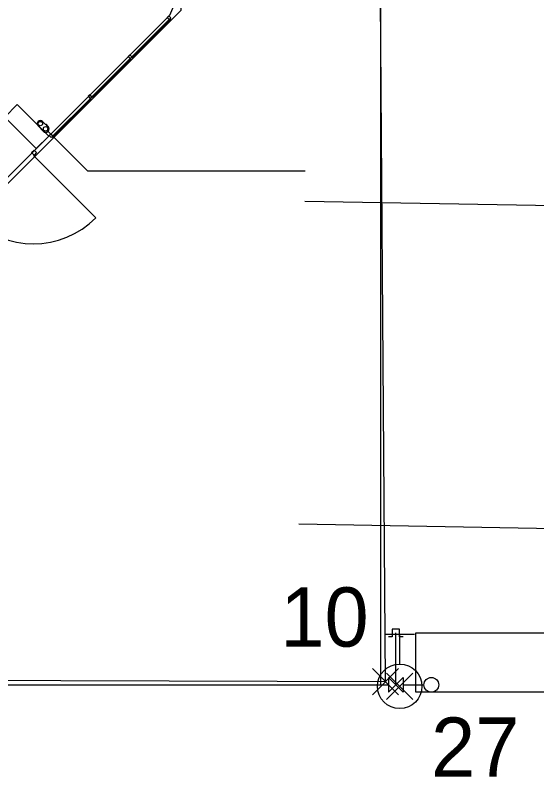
# Model space of a CAD drawing. Extents: x -263964 to -263544, y -1242317 to -1242020.
# Drawn here: x -263800.48 to -263782.89, y -1242253.24 to -1242227.54 of the extents above; entities that cross this region are included whole.
import ezdxf

# ---------------------------------------------------------------- set-up
doc = ezdxf.new("R2010")
doc.units = 0
for name, color, linetype in [('KFA_KOORDINACNA_SITUACIA_DSP_SEDA', 7, 'Continuous'), ('KFA_SO_50-2_POZIARNY_VODOVOD_BODY', 7, 'Continuous'), ('KFA_SO_50-2_POZIARNY_VODOVOD_NADZEMNE_PRVKY', 7, 'Continuous'), ('KFA_SO_50-2_POZIARNY_VODOVOD_TRASA', 7, 'Continuous')]:
    doc.layers.add(name, color=color, linetype=linetype)

msp = doc.modelspace()

# ---------------------------------------------------------------- linework, layer by layer
at = {"layer": 'KFA_KOORDINACNA_SITUACIA_DSP_SEDA'}
for p, q in [((-263788.143, -1242250.14), (-263788.143, -1242082.64)), ((-263795.043, -1242226.995), (-263795.272, -1242227.55)), ((-263795.272, -1242227.55), (-263808.8, -1242241.078)), ((-263796.558, -1242228.963), (-263795.25, -1242227.654)), ((-263795.232, -1242227.672), (-263796.541, -1242228.98)), ((-263795.297, -1242227.56), (-263795.354, -1242227.617)), ((-263795.354, -1242227.617), (-263795.283, -1242227.688)), ((-263795.227, -1242227.631), (-263795.297, -1242227.56)), ((-263795.283, -1242227.688), (-263795.255, -1242227.659)), ((-263795.255, -1242227.659), (-263795.227, -1242227.631)), ((-263795.25, -1242227.654), (-263795.232, -1242227.672)), ((-263796.59, -1242228.994), (-263797.898, -1242230.303)), ((-263797.881, -1242230.32), (-263796.572, -1242229.012)), ((-263796.617, -1242228.879), (-263796.673, -1242228.936)), ((-263796.673, -1242228.936), (-263796.602, -1242229.007)), ((-263796.546, -1242228.95), (-263796.617, -1242228.879)), ((-263796.602, -1242229.007), (-263796.574, -1242228.978)), ((-263796.572, -1242229.012), (-263796.59, -1242228.994)), ((-263796.574, -1242228.978), (-263796.546, -1242228.95)), ((-263796.541, -1242228.98), (-263796.558, -1242228.963)), ((-263797.961, -1242230.223), (-263798.017, -1242230.28)), ((-263798.017, -1242230.28), (-263797.946, -1242230.351)), ((-263797.89, -1242230.294), (-263797.961, -1242230.223)), ((-263797.946, -1242230.351), (-263797.918, -1242230.322)), ((-263797.918, -1242230.322), (-263797.89, -1242230.294)), ((-263797.898, -1242230.303), (-263797.881, -1242230.32)), ((-263800.834, -1242230.985), (-263800.41, -1242230.561)), ((-263800.41, -1242230.561), (-263799.349, -1242231.622)), ((-263797.934, -1242230.338), (-263799.242, -1242231.647)), ((-263799.225, -1242231.664), (-263797.916, -1242230.356)), ((-263797.916, -1242230.356), (-263797.934, -1242230.338)), ((-263799.774, -1242232.046), (-263800.834, -1242230.985)), ((-263799.705, -1242231.275), (-263799.617, -1242231.364)), ((-263799.559, -1242231.13), (-263799.471, -1242231.218)), ((-263799.471, -1242231.218), (-263799.451, -1242231.218)), ((-263799.373, -1242231.296), (-263799.451, -1242231.218)), ((-263799.451, -1242231.218), (-263799.373, -1242231.296)), ((-263799.617, -1242231.364), (-263799.617, -1242231.383)), ((-263799.617, -1242231.383), (-263799.538, -1242231.462)), ((-263799.402, -1242231.432), (-263798.041, -1242232.793)), ((-263799.28, -1242231.543), (-263799.336, -1242231.599)), ((-263799.336, -1242231.599), (-263799.266, -1242231.67)), ((-263799.209, -1242231.613), (-263799.28, -1242231.543)), ((-263799.237, -1242231.642), (-263799.209, -1242231.613)), ((-263799.349, -1242231.622), (-263799.774, -1242232.046)), ((-263799.266, -1242231.67), (-263799.237, -1242231.642)), ((-263799.242, -1242231.647), (-263799.225, -1242231.664)), ((-263799.929, -1242232.178), (-263799.844, -1242232.093)), ((-263799.844, -1242232.093), (-263799.759, -1242232.178)), ((-263799.844, -1242232.263), (-263799.929, -1242232.178)), ((-263799.844, -1242232.263), (-263799.862, -1242232.281)), ((-263799.862, -1242232.281), (-263797.758, -1242234.384)), ((-263799.759, -1242232.178), (-263799.844, -1242232.263)), ((-263798.041, -1242232.793), (-263790.695, -1242232.793)), ((-263781.818, -1242233.99), (-263790.714, -1242233.827)), ((-263781.818, -1242244.885), (-263790.914, -1242244.718)), ((-263787.768, -1242248.265), (-263787.768, -1242248.515)), ((-263787.518, -1242248.265), (-263787.768, -1242248.265)), ((-263787.518, -1242248.515), (-263787.518, -1242248.265)), ((-263787.768, -1242248.515), (-263787.893, -1242248.515)), ((-263787.643, -1242250.14), (-263787.643, -1242248.39)), ((-263787.393, -1242248.515), (-263787.518, -1242248.515)), ((-263787.893, -1242250.39), (-263787.393, -1242249.89)), ((-263787.893, -1242249.89), (-263787.893, -1242250.39)), ((-263787.393, -1242250.39), (-263787.893, -1242249.89)), ((-263787.393, -1242249.89), (-263787.393, -1242250.39)), ((-263924.143, -1242250.14), (-263788.143, -1242250.14)), ((-263788.143, -1242250.14), (-263787.893, -1242250.14)), ((-263788.143, -1242250.14), (-263787.893, -1242250.14)), ((-263787.393, -1242250.14), (-263786.693, -1242250.14))]:
    msp.add_line(p, q, dxfattribs=at)
msp.add_lwpolyline([(-263794.893, -1242227.382), (-263808.968, -1242241.457), (-263894.968, -1242241.457), (-263909.043, -1242227.382), (-263909.043, -1242196.333), (-263914.143, -1242196.333), (-263914.143, -1242132.433), (-263909.043, -1242132.433), (-263909.043, -1242101.382), (-263894.968, -1242087.307), (-263808.968, -1242087.307), (-263794.893, -1242101.382), (-263794.893, -1242227.382)], dxfattribs=at)
msp.add_lwpolyline([(-263786.968, -1242248.382), (-263781.968, -1242248.382), (-263781.968, -1242250.382), (-263786.968, -1242250.382)], close=True, dxfattribs=at)
for centre, radius in [((-263799.632, -1242231.202), 0.075), ((-263799.455, -1242231.379), 0.075), ((-263786.443, -1242250.14), 0.25)]:
    msp.add_circle(centre, radius, dxfattribs=at)
for centre, radius, start, end in [((-263799.632, -1242231.202), 0.103, 45, 225), ((-263799.455, -1242231.379), 0.117, 225, 45), ((-263799.862, -1242232.281), 2.975, 224.9999, 314.9999)]:
    msp.add_arc(centre, radius, start, end, dxfattribs=at)
at = {"layer": 'KFA_SO_50-2_POZIARNY_VODOVOD_BODY'}
for p, q in [((-263788.432, -1242250.474), (-263787.548, -1242249.59)), ((-263787.548, -1242250.474), (-263788.432, -1242249.59)), ((-263787.953, -1242250.632), (-263787.069, -1242249.748)), ((-263787.069, -1242250.632), (-263787.953, -1242249.748)), ((-263787.99, -1242250.032), (-263787.99, -1242250.032)), ((-263787.511, -1242250.19), (-263787.511, -1242250.19))]:
    msp.add_line(p, q, dxfattribs=at)
at = {"layer": 'KFA_SO_50-2_POZIARNY_VODOVOD_NADZEMNE_PRVKY'}
for points in [[(-263787.011, -1242248.44), (-263788.011, -1242248.44)], [(-263787.511, -1242249.44), (-263787.511, -1242248.44)]]:
    msp.add_lwpolyline(points, dxfattribs=at)
msp.add_circle((-263787.511, -1242250.19), 0.75, dxfattribs=at)
at = {"layer": 'KFA_SO_50-2_POZIARNY_VODOVOD_TRASA'}
msp.add_lwpolyline([(-263924.931, -1242185.127), (-263924.146, -1242197.091), (-263924.296, -1242220.899), (-263924.1, -1242250.121), (-263913.986, -1242249.798), (-263886.91, -1242249.876), (-263867.714, -1242249.83), (-263837.257, -1242249.836), (-263828.162, -1242249.901), (-263787.99, -1242250.032), (-263788.202, -1242220.837), (-263788.195, -1242200.509), (-263788.092, -1242179.915), (-263788.062, -1242148.958), (-263787.919, -1242127.952), (-263787.952, -1242110.966), (-263788.129, -1242082.536), (-263828.429, -1242082.723), (-263836.783, -1242082.559), (-263867.306, -1242082.615), (-263886.71, -1242082.472), (-263924.08, -1242082.613), (-263924.644, -1242106.322), (-263924.479, -1242117.427)], close=True, dxfattribs=at)

# ---------------------------------------------------------------- texts
at = {"layer": 'KFA_SO_50-2_POZIARNY_VODOVOD_BODY'}
for s, p in [('10', (-263791.534, -1242248.851)), ('27', (-263786.454, -1242253.242))]:
    msp.add_text(s, height=2, dxfattribs=at).set_placement(p)

doc.saveas('drawing.dxf')
